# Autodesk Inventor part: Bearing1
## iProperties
IsCustomPart: 0
Created: 2009-02
Part Number: Bearing1
Material: Steel, Mild
Description: Magneto Ball Bearing
Document SubType Name: Modeling
Standard: DIN 615
Designer: 904Chiaki
Standards Organization: DIN
Language: en-US
Size Designation: L 25 - 25 x 52 x 15
Categories: <MemberInstance><Categories><Category DisplayName="Shaft Parts" InternalName="7f7aeb1f-a693-4053-b835-cee3144e0d98" Mnemonic="SHFT"><Category DisplayName="Beari
Density: 1 g/cm^3
Author: 904Chiaki
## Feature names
1. Body [Revolution]
2. Fillet1
3. Ball [Revolution]
4. Balls [Circular Pattern]
